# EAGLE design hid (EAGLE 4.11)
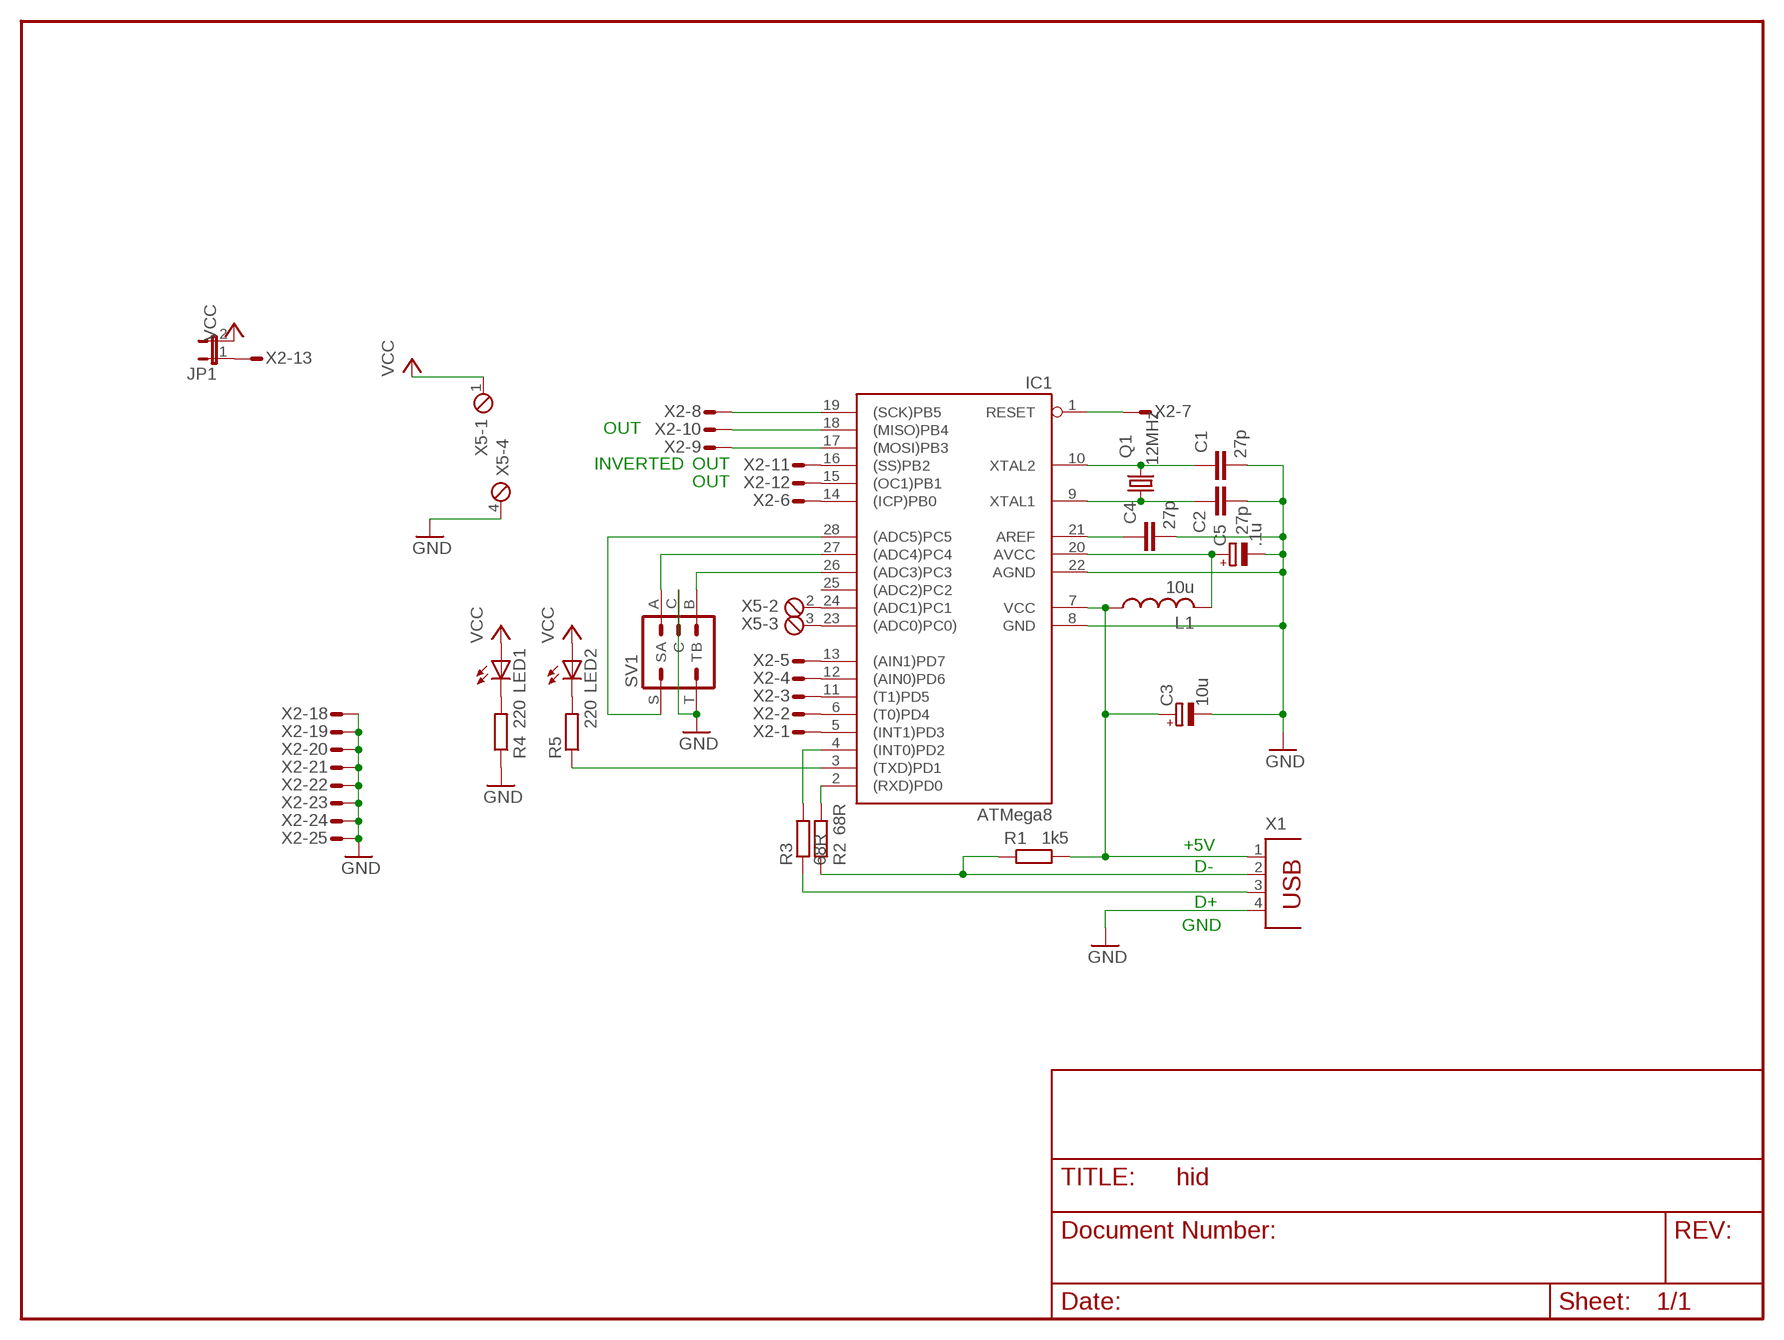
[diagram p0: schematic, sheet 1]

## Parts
C1  27p  C-EU025-024X044  [C025-024X044]
C2  27p  C-EU025-024X044  [C025-024X044]
C3  10u  CPOL-EUE2.5-5  [E2,5-5]
C4  27p  C-EU025-024X044  [C025-024X044]
C5  .1u  CPOL-EUE2.5-5  [E2,5-5]
IC1  ATMega8  AT90S4433P  [DIL28-3]
JP1  JP1E  [JP1]
L1  10u  L-US0204/7  [0204/7]
LED1  LED3MM  [LED3MM]
LED2  LED3MM  [LED3MM]
Q1  12MHz  CRYTALHC49S  [HC49/S]
R1  1k5  R-EU_0309/12  [0309/12]
R2  68R  R-EU_0309/12  [0309/12]
R3  68R  R-EU_0309/12  [0309/12]
R4  220  R-EU_0309/12  [0309/12]
R5  220  R-EU_0309/12  [0309/12]
SV1  ENCODER  [ROTARY]
X1  PN61729  [PN61729]
X2  M25HPS  [M25HP]
X5  MPT4  [4POL254]

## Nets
AREF: C4.1 IC1.21(AREF)
AVCC [pwr]: C5.+ IC1.20(AVCC) L1.2
GND: C1.2 C2.2 C3.- C4.2 C5.- IC1.8(GND) IC1.22(AGND) R4.1 SV1.C SV1.T X1.4 X2.18 X2.19 X2.20 X2.21 X2.22 X2.23 X2.24 X2.25 X5.4
N$1: IC1.1(RESET) X2.7
N$2: IC1.19((SCK)PB5) X2.8
N$3: IC1.17((MOSI)PB3) X2.9
N$4: IC1.18((MISO)PB4) X2.10
N$5: IC1.16((SS)PB2) X2.11
N$6: IC1.15((OC1)PB1) X2.12
N$7: IC1.14((ICP)PB0) X2.6
N$8: IC1.13((AIN1)PD7) X2.5
N$9: IC1.12((AIN0)PD6) X2.4
N$10: IC1.11((T1)PD5) X2.3
N$11: IC1.6((T0)PD4) X2.2
N$12: IC1.5((INT1)PD3) X2.1
N$13: IC1.3((TXD)PD1) R5.1
N$14: IC1.28((ADC5)PC5) SV1.S
N$15: IC1.27((ADC4)PC4) SV1.A
N$16: IC1.26((ADC3)PC3) SV1.B
N$17: JP1.1 X2.13
N$18: R1.1 R2.1 X1.2
N$19: R3.1 X1.3
N$20: IC1.4((INT0)PD2) R3.2
N$21: C1.1 IC1.10(XTAL2) Q1.2
N$22: C2.1 IC1.9(XTAL1) Q1.1
N$23: IC1.2((RXD)PD0) R2.2
N$24: IC1.24((ADC1)PC1) X5.2
N$25: IC1.23((ADC0)PC0)) X5.3
N$27: LED1.K(C) R4.2
N$28: LED2.K(C) R5.2
VCC [pwr]: C3.+ IC1.7(VCC) JP1.2 L1.1 LED1.A LED2.A R1.2 X1.1 X5.1
Unconnected: IC1.25((ADC2)PC2) X2.14 X2.15 X2.16 X2.17

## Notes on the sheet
- OUT
- INVERTED | OUT
- OUT
- +5V
- D-
- D+
- GND

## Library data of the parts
C1 C2 C4 = rcl:C-EU: CAPACITOR, European symbol
C3 C5 = rcl:CPOL-EU: POLARIZED CAPACITOR, European symbol
IC1 = atmel:AT90S4433: MICROCONTROLLER 4 Kbytes FLASH 128 bytes SRAM 256 bytes EEPROM UART 6-channel 10 bit ADC
JP1 = jumper:JP1E: JUMPER
L1 = rcl:L-US: INDUCTOR, American symbol
LED1 LED2 = led:LED: LED
Q1 = crystal:CRYTAL: CRYSTAL
R1-R5 = rcl:R-EU_: RESISTOR, European symbol
SV1 = bourns-encoder:ENCODER: PIN HEADER
X1 = con-berg:PN61729: BERG
X2 = con-subd:M25?S: SUB-D
X5 = con-phoenix-254:MPT4: PHOENIX CONNECTOR

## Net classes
0 default: width 0.305 mm, drill 0.305 mm
1 pwr: width 0.635 mm

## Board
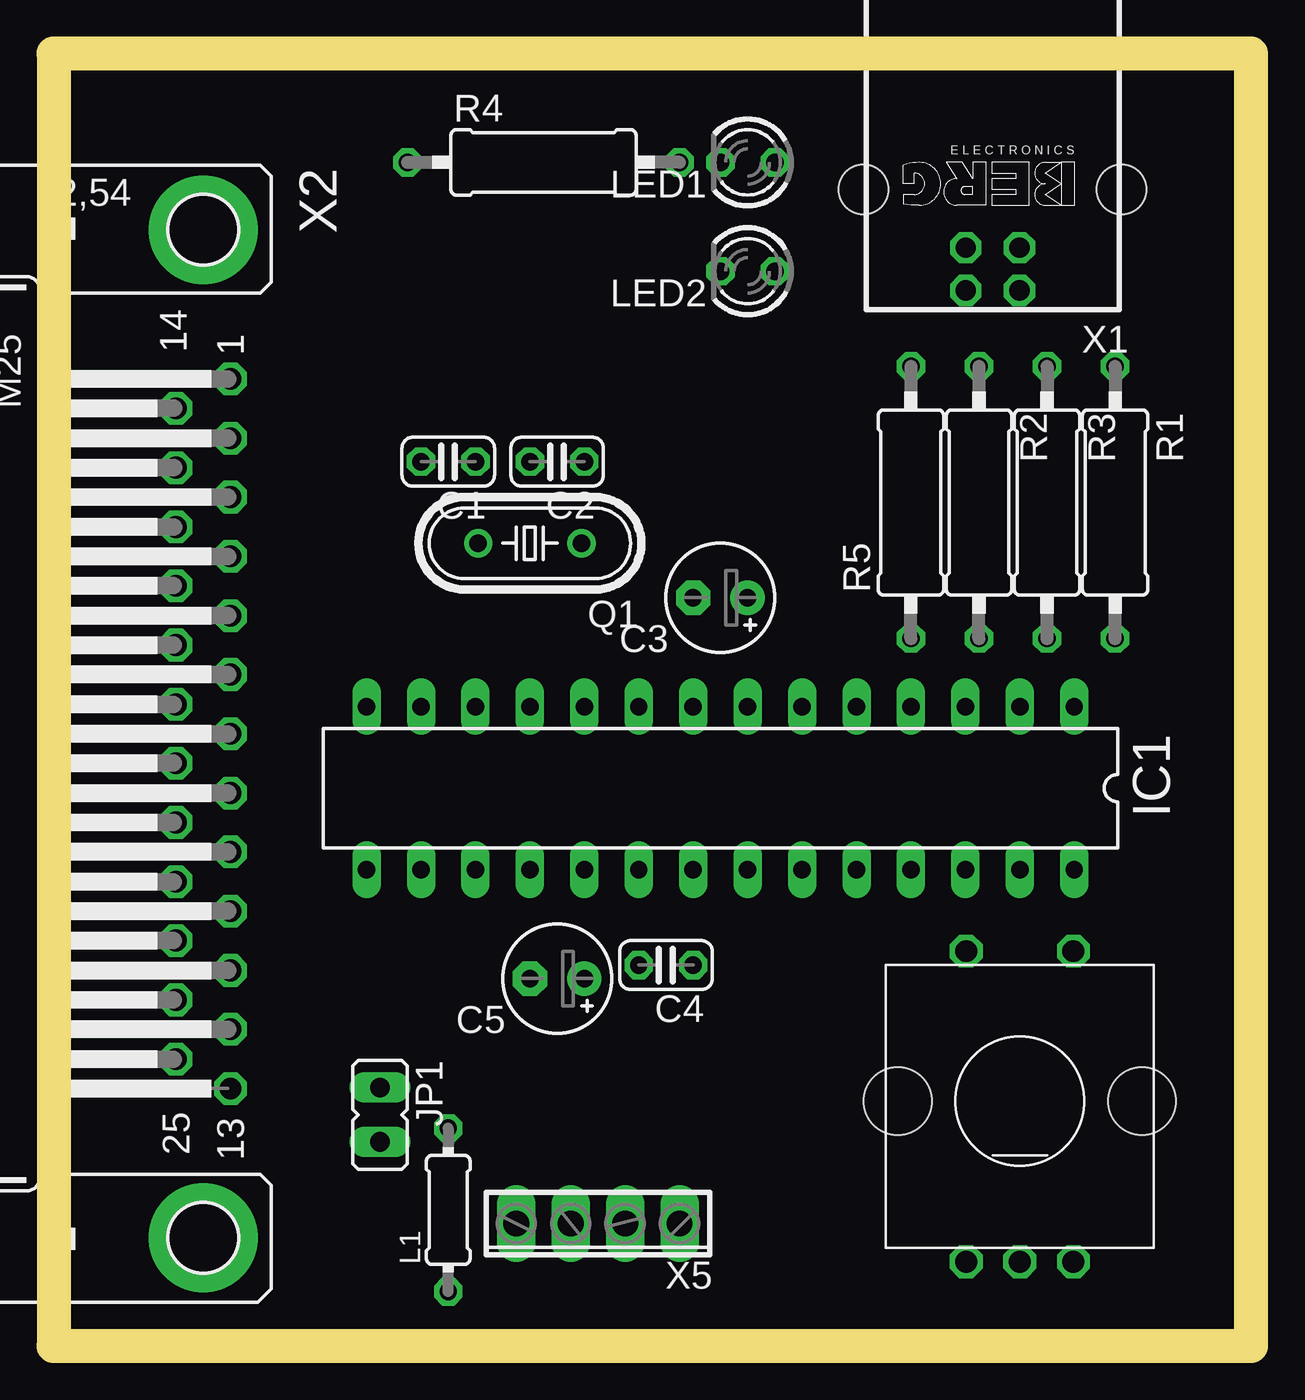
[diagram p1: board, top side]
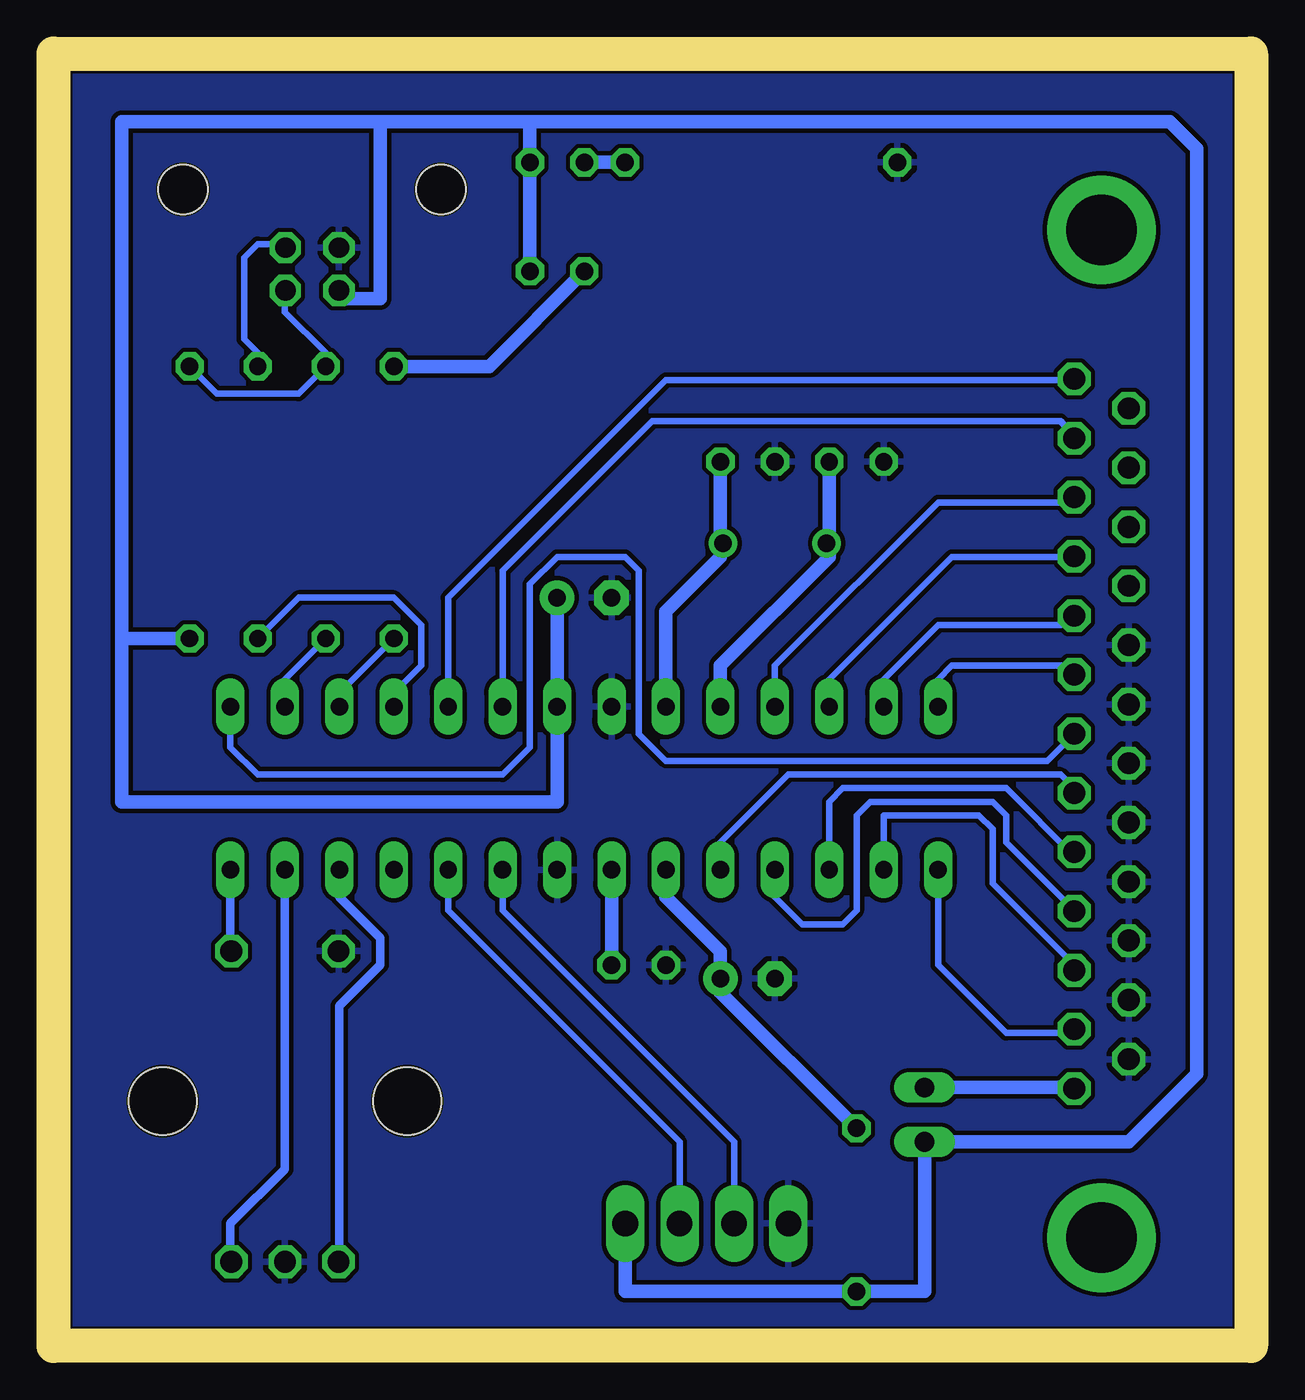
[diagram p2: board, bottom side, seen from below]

Size 55.88 x 60.32 mm. Coordinates in mm from the lower left corner, seen from the top.
Outline: 0,0 55.88,0 55.88,60.32 0,60.32 0,0
Copper layers (1*16): Top 0.035mm / dielectric 1.5mm / Bottom 0.035mm
Design rules "default": minimum track width 10mil, minimum drill 24mil, track to track 8mil, track to pad 8mil, pad to pad 8mil, via to via 8mil, smd to smd 8mil, copper to edge 4mil, drill to drill 8mil, minimum pad ring 10mil, minimum via ring 8mil, stop-mask expansion 4mil, vias tented up to drill 0mil, thermal gap 10mil

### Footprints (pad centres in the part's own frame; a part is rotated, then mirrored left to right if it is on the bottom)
C025-024X044 = drill 0.813 octagon: 1 -1.27,0; 2 1.27,0
E2,5-5 = drill 0.813 pad 1.6 round: + -1.27,0 | drill 0.813 pad 1.6 octagon: - 1.27,0
DIL28-3 = drill 0.813 long: 1 -16.51,-3.81; 2 -13.97,-3.81; 3 -11.43,-3.81; 4 -8.89,-3.81; 5 -6.35,-3.81; 6 -3.81,-3.81; 7 -1.27,-3.81; 8 1.27,-3.81; 9 3.81,-3.81; 10 6.35,-3.81; 11 8.89,-3.81; 12 11.43,-3.81; 13 13.97,-3.81; 14 16.51,-3.81; 15 16.51,3.81; 16 13.97,3.81; 17 11.43,3.81; 18 8.89,3.81; 19 6.35,3.81; 20 3.81,3.81; 21 1.27,3.81; 22 -1.27,3.81; 23 -3.81,3.81; 24 -6.35,3.81; 25 -8.89,3.81; 26 -11.43,3.81; 27 -13.97,3.81; 28 -16.51,3.81
JP1 = drill 0.914 long: 1 0,-1.27; 2 0,1.27
0204/7 = drill 0.813 octagon: 1 -3.81,0; 2 3.81,0
LED3MM = drill 0.813 octagon: A -1.27,0; K 1.27,0
HC49/S = drill 0.813 round: 1 -2.413,0; 2 2.413,0
0309/12 = drill 0.813 octagon: 1 -6.35,0; 2 6.35,0
ROTARY = drill 1.016 octagon: A 2.5,-7.5; B -2.5,-7.5; C 0,-7.5; S 2.5,7; T -2.5,7 | hole 3.16: -5.7,0; 5.7,0
PN61729 = drill 0.95 octagon: 1 1.25,4.71; 2 -1.25,4.71; 3 -1.25,2.71; 4 1.25,2.71 | hole 2.3: -6.02,0; 6.02,0
M25HP = drill 1.016 octagon: 1 -16.561,1.27; 2 -13.792,1.27; 3 -11.049,1.27; 4 -8.28,1.27; 5 -5.512,1.27; 6 -2.769,1.27; 7 0,1.27; 8 2.769,1.27; 9 5.512,1.27; 10 8.28,1.27; 11 11.049,1.27; 12 13.792,1.27; 13 16.561,1.27; 14 -15.189,-1.27; 15 -12.421,-1.27; 16 -9.652,-1.27; 17 -6.909,-1.27; 18 -4.14,-1.27; 19 -1.372,-1.27; 20 1.372,-1.27; 21 4.14,-1.27; 22 6.909,-1.27; 23 9.652,-1.27; 24 12.421,-1.27; 25 15.189,-1.27 | drill 3.302 pad 5.08 round: G1 -23.52,0; G2 23.52,0
4POL254 = drill 1.2 long: 1 -3.81,0; 2 -1.27,0; 3 1.27,0; 4 3.81,0

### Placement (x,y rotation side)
C1  18.41,41.27 180 top
C2  23.49,41.27 180 top
C3  31.11,34.92 180 top
C4  28.57,17.78 180 top
C5  23.49,17.15 180 top
IC1  31.11,26.04 180 top
JP1  15.24,10.79 180 top
L1  18.41,6.35 90 top
LED1  32.39,55.24 180 top
LED2  32.39,50.16 180 top
Q1  22.22,37.46 180 top
R1  49.53,39.37 270 top
R2  43.18,39.37 270 top
R3  46.36,39.37 270 top
R4  22.86,55.24 0 top
R5  40.01,39.37 90 top
SV1  45.09,11.43 0 top
X1  43.82,53.98 180 top
X2  6.99,28.58 270 top
X5  25.4,5.71 180 top

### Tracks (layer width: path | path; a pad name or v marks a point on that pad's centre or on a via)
AREF
  Bottom 0.635: C4.1 IC1.21
AVCC
  Bottom 0.635: IC1.20 27.3,20.96 24.76,18.42 C5.+ 24.76,16.51 L1.2
GND
  pour Bottom: 0,59.69 56.52,59.69 56.52,0.64 0,0
N$1
  Bottom 0.305: X2.7 9.53,27.31 27.3,27.31 28.57,28.58 28.57,36.2 29.21,36.83 32.39,36.83 33.66,35.56 33.66,27.94 34.93,26.67 46.36,26.67 47.62,27.94 IC1.1
N$2
  Bottom 0.305: IC1.19 24.76,23.5 21.59,26.67 8.89,26.67 8.26,26.04 X2.8
N$3
  Bottom 0.305: IC1.17 19.68,25.4 19.05,26.04 11.43,26.04 8.26,22.86 X2.9
N$4
  Bottom 0.305: X2.10 8.26,20.32 11.43,23.5 11.43,24.77 12.06,25.4 17.78,25.4 18.41,24.77 18.41,20.32 19.05,19.69 20.95,19.69 22.22,20.96 IC1.18
N$5
  Bottom 0.305: IC1.16 17.14,24.77 12.7,24.77 12.06,24.13 12.06,21.59 8.26,17.78 X2.11
N$6
  Bottom 0.305: IC1.15 14.61,17.78 11.43,14.61 8.26,14.61 X2.12
N$7
  Bottom 0.305: IC1.14 14.61,31.12 13.97,31.75 8.26,31.75 X2.6
N$8
  Bottom 0.305: IC1.13 17.14,31.12 14.61,33.66 8.89,33.66 X2.5
N$9
  Bottom 0.305: IC1.12 19.68,31.12 13.97,36.83 8.89,36.83 X2.4
N$10
  Bottom 0.305: IC1.11 22.22,31.75 14.61,39.37 8.89,39.37 X2.3
N$11
  Bottom 0.305: IC1.6 34.93,36.2 27.94,43.18 8.89,43.18 X2.2
N$12
  Bottom 0.305: IC1.5 37.47,34.92 27.3,45.09 8.89,45.09 X2.1
N$13
  Bottom 0.305: IC1.3 42.55,30.48 R5.1
N$14
  Bottom 0.406: SV1.S 47.61,18.43 47.62,18.42 IC1.28
N$15
  Bottom 0.406: IC1.27 45.09,8.26 47.62,5.71 47.62,3.81 47.59,3.85 SV1.A
N$16
  Bottom 0.406: IC1.26 42.55,20.96 40.64,19.05 40.64,17.78 42.55,15.88 42.55,3.81 42.59,3.85 SV1.B
N$17
  Bottom 0.635: X2.13 8.31,12.06 JP1.1
N$18
  Bottom 0.305: R1.1 48.26,44.45 44.45,44.45 R2.1 43.18,46.35 45.09,48.26 45.09,48.89 45.06,48.92 45.06,49.5 45.07,49.51 | 45.07,49.51 X1.2 | 45.07,49.51 45.09,49.53
N$19
  Bottom 0.305: R3.1 46.36,46.35 46.99,46.99 46.99,50.8 46.36,51.43 45.09,51.43 | 45.09,51.43 45.06,51.41 X1.3 | X1.3 45.07,51.41 45.09,51.43
N$20
  Bottom 0.305: IC1.4 40.01,30.48 38.73,31.75 38.73,33.66 40.01,34.92 44.45,34.92 R3.2
N$21
  Bottom 0.305: 19.68,37.46 Q1.2
  Bottom 0.635: C1.1 19.68,37.46 19.68,36.83 24.76,31.75 IC1.10
N$22
  Bottom 0.305: 24.76,37.46 Q1.1
  Bottom 0.635: C2.1 24.76,37.46 24.76,36.83 27.3,34.29 IC1.9
N$23
  Bottom 0.305: IC1.2 45.09,31.12 R2.2
N$24
  Bottom 0.305: IC1.24 37.47,20.32 26.67,9.53 X5.2
N$25
  Bottom 0.305: IC1.23 34.93,20.32 24.13,9.53 X5.3
N$27
  Bottom 0.635: R4.2 LED1.K
N$28
  Bottom 0.635: R5.2 35.56,45.72 LED2.K
VCC
  Bottom 0.635: 40.64,57.15 40.64,48.89 42.55,48.89 42.57,48.91 X1.1 | 40.64,57.15 52.71,57.15 52.71,33.02 | 52.71,33.02 52.71,25.4 32.39,25.4 IC1.7 C3.+ | X5.1 29.21,2.54 L1.1 15.24,2.54 JP1.2 5.71,9.53 2.54,12.7 2.54,55.88 3.81,57.15 33.66,57.15 | LED2.A LED1.A 33.66,57.15 | 33.66,57.15 40.64,57.15 | 52.71,33.02 R1.2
